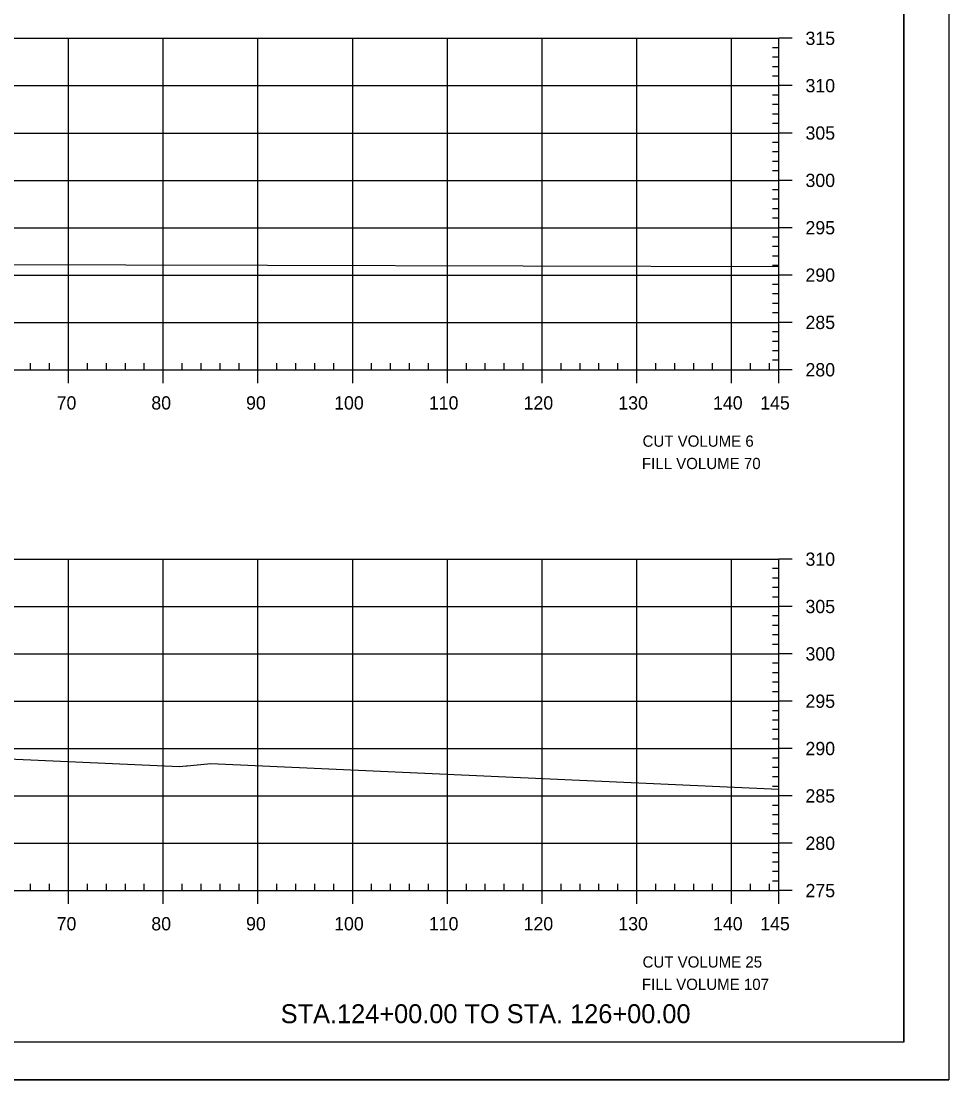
# Model space of a CAD drawing. Extents: x 1370843 to 1371177, y 380307 to 382654.
# Drawn here: x 1371078.7 to 1371176.6, y 382227.5 to 382339.3 of the extents above; entities that cross this region are included whole.
import ezdxf

# ---------------------------------------------------------------- set-up
doc = ezdxf.new("R2010")
doc.units = 0
for name, color, linetype in [('R_Axis', 7, 'Continuous'), ('R_Axis Annot', 7, 'Continuous'), ('R_Border', 7, 'Continuous'), ('R_Border Notes', 7, 'Continuous'), ('R_Draft', 7, 'Continuous'), ('R_Exist Surface', 7, 'Continuous'), ('R_Grid', 7, 'Continuous'), ('R_No Plot', 7, 'Continuous')]:
    doc.layers.add(name, color=color, linetype=linetype)

msp = doc.modelspace()

# ---------------------------------------------------------------- linework, layer by layer
at = {"layer": 'R_Axis'}
for p, q in [((1371158.71, 382302.49), (1371158.71, 382337.49)), ((1371160.11, 382337.49), (1371158.71, 382337.49)), ((1371158.71, 382336.49), (1371158.01, 382336.49)), ((1371158.71, 382335.49), (1371158.01, 382335.49)), ((1371158.71, 382334.49), (1371158.01, 382334.49)), ((1371158.71, 382333.49), (1371158.01, 382333.49)), ((1371160.11, 382332.49), (1371158.71, 382332.49)), ((1371158.71, 382331.49), (1371158.01, 382331.49)), ((1371158.71, 382330.49), (1371158.01, 382330.49)), ((1371158.71, 382329.49), (1371158.01, 382329.49)), ((1371158.71, 382328.49), (1371158.01, 382328.49)), ((1371160.11, 382327.49), (1371158.71, 382327.49)), ((1371158.71, 382326.49), (1371158.01, 382326.49)), ((1371158.71, 382325.49), (1371158.01, 382325.49)), ((1371158.71, 382324.49), (1371158.01, 382324.49)), ((1371158.71, 382323.49), (1371158.01, 382323.49)), ((1371160.11, 382322.49), (1371158.71, 382322.49)), ((1371158.71, 382321.49), (1371158.01, 382321.49)), ((1371158.71, 382320.49), (1371158.01, 382320.49)), ((1371158.71, 382319.49), (1371158.01, 382319.49)), ((1371158.71, 382318.49), (1371158.01, 382318.49)), ((1371158.71, 382316.49), (1371158.01, 382316.49)), ((1371160.11, 382317.49), (1371158.71, 382317.49)), ((1371158.71, 382315.49), (1371158.01, 382315.49)), ((1371158.71, 382314.49), (1371158.01, 382314.49)), ((1371158.71, 382313.49), (1371158.01, 382313.49)), ((1371160.11, 382312.49), (1371158.71, 382312.49)), ((1371158.71, 382311.49), (1371158.01, 382311.49)), ((1371158.71, 382310.49), (1371158.01, 382310.49)), ((1371158.71, 382309.49), (1371158.01, 382309.49)), ((1371158.71, 382308.49), (1371158.01, 382308.49)), ((1371158.71, 382306.49), (1371158.01, 382306.49)), ((1371160.11, 382307.49), (1371158.71, 382307.49)), ((1371158.71, 382305.49), (1371158.01, 382305.49)), ((1371158.71, 382304.49), (1371158.01, 382304.49)), ((1371079.71, 382302.49), (1371079.71, 382303.19)), ((1371081.71, 382302.49), (1371081.71, 382303.19)), ((1371085.71, 382302.49), (1371085.71, 382303.19)), ((1371087.71, 382302.49), (1371087.71, 382303.19)), ((1371089.71, 382302.49), (1371089.71, 382303.19)), ((1371091.71, 382302.49), (1371091.71, 382303.19)), ((1371095.71, 382302.49), (1371095.71, 382303.19)), ((1371097.71, 382302.49), (1371097.71, 382303.19)), ((1371099.71, 382302.49), (1371099.71, 382303.19)), ((1371101.71, 382302.49), (1371101.71, 382303.19)), ((1371105.71, 382302.49), (1371105.71, 382303.19)), ((1371107.71, 382302.49), (1371107.71, 382303.19)), ((1371109.71, 382302.49), (1371109.71, 382303.19)), ((1371111.71, 382302.49), (1371111.71, 382303.19)), ((1371115.71, 382302.49), (1371115.71, 382303.19)), ((1371117.71, 382302.49), (1371117.71, 382303.19)), ((1371119.71, 382302.49), (1371119.71, 382303.19)), ((1371121.71, 382302.49), (1371121.71, 382303.19)), ((1371125.71, 382302.49), (1371125.71, 382303.19)), ((1371127.71, 382302.49), (1371127.71, 382303.19)), ((1371129.71, 382302.49), (1371129.71, 382303.19)), ((1371131.71, 382302.49), (1371131.71, 382303.19)), ((1371135.71, 382302.49), (1371135.71, 382303.19)), ((1371137.71, 382302.49), (1371137.71, 382303.19)), ((1371139.71, 382302.49), (1371139.71, 382303.19)), ((1371141.71, 382302.49), (1371141.71, 382303.19)), ((1371145.71, 382302.49), (1371145.71, 382303.19)), ((1371147.71, 382302.49), (1371147.71, 382303.19)), ((1371149.71, 382302.49), (1371149.71, 382303.19)), ((1371151.71, 382302.49), (1371151.71, 382303.19)), ((1371155.71, 382302.49), (1371155.71, 382303.19)), ((1371157.71, 382302.49), (1371157.71, 382303.19)), ((1371158.71, 382303.49), (1371158.01, 382303.49)), ((1370868.71, 382302.49), (1371158.71, 382302.49)), ((1371083.71, 382301.09), (1371083.71, 382302.49)), ((1371093.71, 382301.09), (1371093.71, 382302.49)), ((1371103.71, 382301.09), (1371103.71, 382302.49)), ((1371113.71, 382301.09), (1371113.71, 382302.49)), ((1371123.71, 382301.09), (1371123.71, 382302.49)), ((1371133.71, 382301.09), (1371133.71, 382302.49)), ((1371143.71, 382301.09), (1371143.71, 382302.49)), ((1371153.71, 382301.09), (1371153.71, 382302.49)), ((1371158.71, 382301.09), (1371158.71, 382302.49)), ((1371160.11, 382302.49), (1371158.71, 382302.49)), ((1371158.71, 382247.49), (1371158.71, 382282.49)), ((1371160.11, 382282.49), (1371158.71, 382282.49)), ((1371158.71, 382281.49), (1371158.01, 382281.49)), ((1371158.71, 382280.49), (1371158.01, 382280.49)), ((1371158.71, 382279.49), (1371158.01, 382279.49)), ((1371158.71, 382278.49), (1371158.01, 382278.49)), ((1371160.11, 382277.49), (1371158.71, 382277.49)), ((1371158.71, 382276.49), (1371158.01, 382276.49)), ((1371158.71, 382275.49), (1371158.01, 382275.49)), ((1371158.71, 382274.49), (1371158.01, 382274.49)), ((1371158.71, 382273.49), (1371158.01, 382273.49)), ((1371160.11, 382272.49), (1371158.71, 382272.49)), ((1371158.71, 382271.49), (1371158.01, 382271.49)), ((1371158.71, 382270.49), (1371158.01, 382270.49)), ((1371158.71, 382269.49), (1371158.01, 382269.49)), ((1371158.71, 382268.49), (1371158.01, 382268.49)), ((1371160.11, 382267.49), (1371158.71, 382267.49)), ((1371158.71, 382266.49), (1371158.01, 382266.49)), ((1371158.71, 382265.49), (1371158.01, 382265.49)), ((1371158.71, 382264.49), (1371158.01, 382264.49)), ((1371158.71, 382263.49), (1371158.01, 382263.49)), ((1371160.11, 382262.49), (1371158.71, 382262.49)), ((1371158.71, 382261.49), (1371158.01, 382261.49)), ((1371158.71, 382260.49), (1371158.01, 382260.49)), ((1371158.71, 382259.49), (1371158.01, 382259.49)), ((1371158.71, 382258.49), (1371158.01, 382258.49)), ((1371160.11, 382257.49), (1371158.71, 382257.49)), ((1371158.71, 382256.49), (1371158.01, 382256.49)), ((1371158.71, 382255.49), (1371158.01, 382255.49)), ((1371158.71, 382254.49), (1371158.01, 382254.49)), ((1371158.71, 382253.49), (1371158.01, 382253.49)), ((1371160.11, 382252.49), (1371158.71, 382252.49)), ((1371158.71, 382251.49), (1371158.01, 382251.49)), ((1371158.71, 382250.49), (1371158.01, 382250.49)), ((1371158.71, 382249.49), (1371158.01, 382249.49)), ((1371158.71, 382248.49), (1371158.01, 382248.49)), ((1370868.71, 382247.49), (1371158.71, 382247.49)), ((1371079.71, 382247.49), (1371079.71, 382248.19)), ((1371081.71, 382247.49), (1371081.71, 382248.19)), ((1371083.71, 382246.09), (1371083.71, 382247.49)), ((1371085.71, 382247.49), (1371085.71, 382248.19)), ((1371087.71, 382247.49), (1371087.71, 382248.19)), ((1371089.71, 382247.49), (1371089.71, 382248.19)), ((1371091.71, 382247.49), (1371091.71, 382248.19)), ((1371093.71, 382246.09), (1371093.71, 382247.49)), ((1371095.71, 382247.49), (1371095.71, 382248.19)), ((1371097.71, 382247.49), (1371097.71, 382248.19)), ((1371099.71, 382247.49), (1371099.71, 382248.19)), ((1371101.71, 382247.49), (1371101.71, 382248.19)), ((1371103.71, 382246.09), (1371103.71, 382247.49)), ((1371105.71, 382247.49), (1371105.71, 382248.19)), ((1371107.71, 382247.49), (1371107.71, 382248.19)), ((1371109.71, 382247.49), (1371109.71, 382248.19)), ((1371111.71, 382247.49), (1371111.71, 382248.19)), ((1371113.71, 382246.09), (1371113.71, 382247.49)), ((1371115.71, 382247.49), (1371115.71, 382248.19)), ((1371117.71, 382247.49), (1371117.71, 382248.19)), ((1371119.71, 382247.49), (1371119.71, 382248.19)), ((1371121.71, 382247.49), (1371121.71, 382248.19)), ((1371123.71, 382246.09), (1371123.71, 382247.49)), ((1371125.71, 382247.49), (1371125.71, 382248.19)), ((1371127.71, 382247.49), (1371127.71, 382248.19)), ((1371129.71, 382247.49), (1371129.71, 382248.19)), ((1371131.71, 382247.49), (1371131.71, 382248.19)), ((1371133.71, 382246.09), (1371133.71, 382247.49)), ((1371135.71, 382247.49), (1371135.71, 382248.19)), ((1371137.71, 382247.49), (1371137.71, 382248.19)), ((1371139.71, 382247.49), (1371139.71, 382248.19)), ((1371141.71, 382247.49), (1371141.71, 382248.19)), ((1371143.71, 382246.09), (1371143.71, 382247.49)), ((1371145.71, 382247.49), (1371145.71, 382248.19)), ((1371147.71, 382247.49), (1371147.71, 382248.19)), ((1371149.71, 382247.49), (1371149.71, 382248.19)), ((1371151.71, 382247.49), (1371151.71, 382248.19)), ((1371153.71, 382246.09), (1371153.71, 382247.49)), ((1371155.71, 382247.49), (1371155.71, 382248.19)), ((1371157.71, 382247.49), (1371157.71, 382248.19)), ((1371158.71, 382246.09), (1371158.71, 382247.49)), ((1371160.11, 382247.49), (1371158.71, 382247.49))]:
    msp.add_line(p, q, dxfattribs=at)
at = {"layer": 'R_Border'}
for q in [(1371171.89, 382436.95), (1370855.71, 382231.49)]:
    msp.add_line((1371171.89, 382231.49), q, dxfattribs=at)
at = {"layer": 'R_Exist Surface'}
for p, q in [((1371104.7, 382313.54), (1371158.71, 382313.39)), ((1371098.72, 382260.91), (1371158.71, 382258.2))]:
    msp.add_line(p, q, dxfattribs=at)
for points in [[(1371074.77, 382313.62), (1371104.7, 382313.54)], [(1370979.57, 382262.87), (1370993.46, 382265.68), (1370995.22, 382265.88), (1370999.76, 382266.4), (1371001.09, 382266.41), (1371011.76, 382266.43), (1371012.89, 382266.37), (1371021.28, 382265.92), (1371027.77, 382265.04), (1371028.02, 382265.01), (1371028.21, 382264.95), (1371032.71, 382263.35), (1371036.77, 382262.74), (1371036.83, 382262.73), (1371038.11, 382262.85), (1371040.6, 382263.09), (1371042.26, 382263.02), (1371055.24, 382262.45), (1371065.53, 382261.92), (1371095.42, 382260.59), (1371096.13, 382260.66), (1371096.24, 382260.67), (1371098.72, 382260.91)]]:
    msp.add_lwpolyline(points, dxfattribs=at)
at = {"layer": 'R_Grid'}
for p, q in [((1370868.71, 382337.49), (1371158.71, 382337.49)), ((1371083.71, 382302.49), (1371083.71, 382337.49)), ((1371093.71, 382302.49), (1371093.71, 382337.49)), ((1371103.71, 382302.49), (1371103.71, 382337.49)), ((1371113.71, 382302.49), (1371113.71, 382337.49)), ((1371123.71, 382302.49), (1371123.71, 382337.49)), ((1371133.71, 382302.49), (1371133.71, 382337.49)), ((1371143.71, 382302.49), (1371143.71, 382337.49)), ((1371153.71, 382302.49), (1371153.71, 382337.49)), ((1371158.71, 382302.49), (1371158.71, 382337.49)), ((1370868.71, 382332.49), (1371158.71, 382332.49)), ((1370868.71, 382327.49), (1371158.71, 382327.49)), ((1370868.71, 382322.49), (1371158.71, 382322.49)), ((1370868.71, 382317.49), (1371158.71, 382317.49)), ((1370868.71, 382312.49), (1371158.71, 382312.49)), ((1370868.71, 382307.49), (1371158.71, 382307.49)), ((1370868.71, 382302.49), (1371158.71, 382302.49)), ((1370868.71, 382282.49), (1371158.71, 382282.49)), ((1371083.71, 382247.49), (1371083.71, 382282.49)), ((1371093.71, 382247.49), (1371093.71, 382282.49)), ((1371103.71, 382247.49), (1371103.71, 382282.49)), ((1371113.71, 382247.49), (1371113.71, 382282.49)), ((1371123.71, 382247.49), (1371123.71, 382282.49)), ((1371133.71, 382247.49), (1371133.71, 382282.49)), ((1371143.71, 382247.49), (1371143.71, 382282.49)), ((1371153.71, 382247.49), (1371153.71, 382282.49)), ((1371158.71, 382247.49), (1371158.71, 382282.49)), ((1370868.71, 382277.49), (1371158.71, 382277.49)), ((1370868.71, 382272.49), (1371158.71, 382272.49)), ((1370868.71, 382267.49), (1371158.71, 382267.49)), ((1370868.71, 382262.49), (1371158.71, 382262.49)), ((1370868.71, 382257.49), (1371158.71, 382257.49)), ((1370868.71, 382252.49), (1371158.71, 382252.49)), ((1370868.71, 382247.49), (1371158.71, 382247.49))]:
    msp.add_line(p, q, dxfattribs=at)
at = {"layer": 'R_No Plot'}
msp.add_line((1370843.31, 382227.51), (1371176.64, 382227.51), dxfattribs=at)
for points in [[(1370843.3, 382440.84), (1371176.64, 382440.84), (1371176.64, 382227.51), (1370843.3, 382227.51)], [(1371089.63, 382436.95), (1371089.63, 382427.07), (1371125.36, 382427.07), (1371125.36, 382424.15), (1371148.56, 382424.15), (1371148.56, 382399.82), (1371171.89, 382399.82), (1371171.89, 382231.49), (1370855.71, 382231.49), (1370855.71, 382436.95)]]:
    msp.add_lwpolyline(points, close=True, dxfattribs=at)

# ---------------------------------------------------------------- texts
at = {"layer": 'R_Axis Annot'}
for s, p in [('315', (1371161.51, 382336.79)), ('310', (1371161.51, 382331.79)), ('305', (1371161.51, 382326.79)), ('300', (1371161.51, 382321.79)), ('295', (1371161.51, 382316.79)), ('290', (1371161.51, 382311.79)), ('285', (1371161.51, 382306.79)), ('280', (1371161.51, 382301.79)), ('70', (1371082.45, 382298.29)), ('80', (1371092.45, 382298.29)), ('90', (1371102.45, 382298.29)), ('100', (1371111.75, 382298.29)), ('110', (1371121.75, 382298.29)), ('120', (1371131.75, 382298.29)), ('130', (1371141.75, 382298.29)), ('140', (1371151.75, 382298.29)), ('145', (1371156.73, 382298.29)), ('310', (1371161.51, 382281.79)), ('305', (1371161.51, 382276.79)), ('300', (1371161.51, 382271.79)), ('295', (1371161.51, 382266.79)), ('290', (1371161.51, 382261.79)), ('285', (1371161.51, 382256.79)), ('280', (1371161.51, 382251.79)), ('275', (1371161.51, 382246.79)), ('70', (1371082.45, 382243.29)), ('80', (1371092.45, 382243.29)), ('90', (1371102.45, 382243.29)), ('100', (1371111.75, 382243.29)), ('110', (1371121.75, 382243.29)), ('120', (1371131.75, 382243.29)), ('130', (1371141.75, 382243.29)), ('140', (1371151.75, 382243.29)), ('145', (1371156.73, 382243.29))]:
    msp.add_text(s, height=1.4, dxfattribs=at).set_placement(p)
at = {"layer": 'R_Border Notes'}
for s, p in [('CUT VOLUME 6', (1371144.31, 382294.36)), ('FILL VOLUME 70', (1371144.24, 382292)), ('CUT VOLUME 25', (1371144.31, 382239.36)), ('FILL VOLUME 107', (1371144.24, 382237))]:
    msp.add_text(s, height=1.1875, dxfattribs=at).set_placement(p)
at = {"layer": 'R_Draft'}
msp.add_text('STA.124+00.00 TO STA. 126+00.00', height=2, dxfattribs=at).set_placement((1371106.11, 382233.49))

doc.saveas('drawing.dxf')
